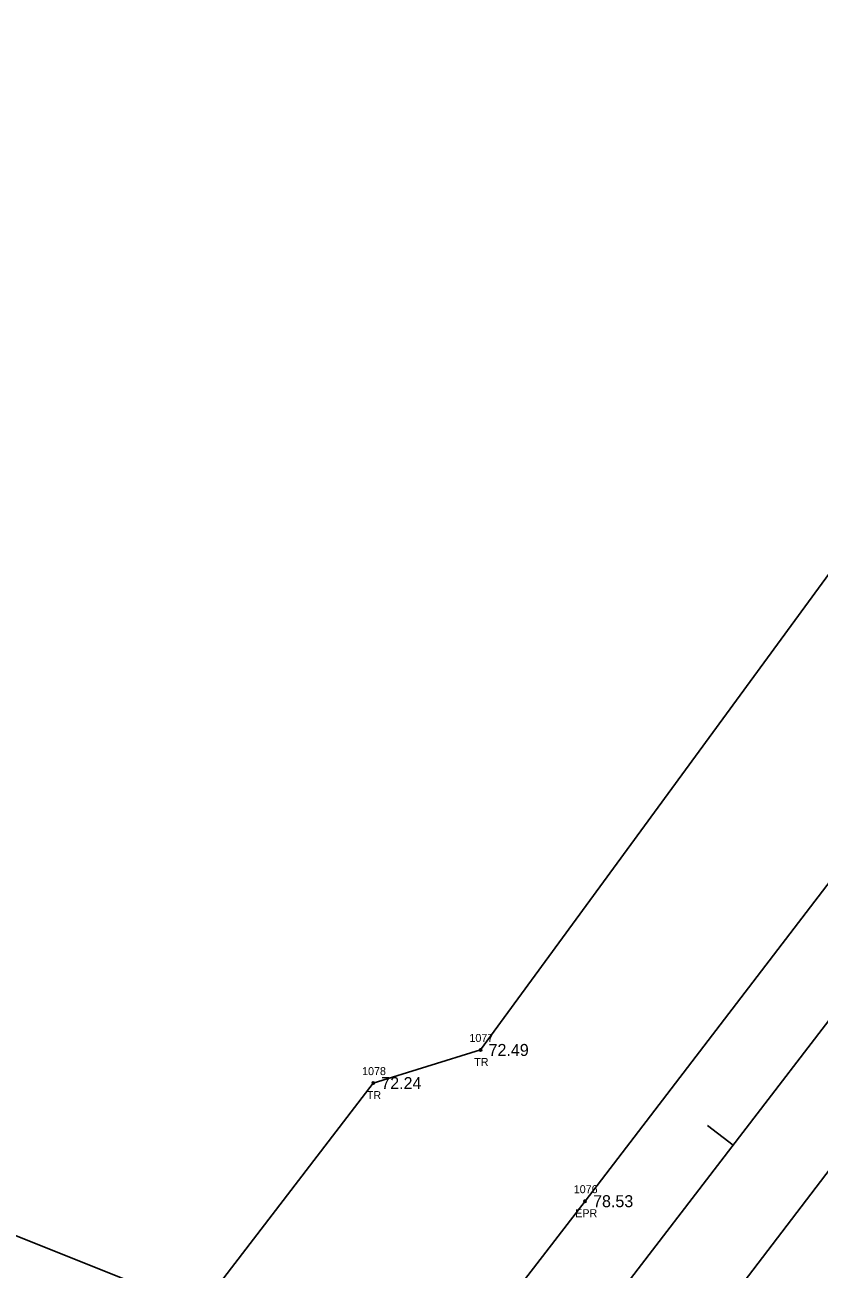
# Model space of a CAD drawing. Extents: x 2505249 to 2506333, y 912937 to 914171.
# Drawn here: x 2505770.9 to 2505870.1, y 913565.9 to 913721.3 of the extents above; entities that cross this region are included whole.
import ezdxf

# ---------------------------------------------------------------- set-up
doc = ezdxf.new("R2010")
doc.units = 0
for name, color, linetype in [('RD_EX_H2O', 7, 'Continuous'), ('RD_EX_Road', 7, 'Continuous'), ('RD_EX_Road_txCode', 7, 'Continuous'), ('RD_EX_TX_Road_ELEV', 7, 'Continuous'), ('RD_EX_TX_VEG_ELEV', 7, 'Continuous'), ('RD_EX_VEG', 7, 'Continuous'), ('RD_EX_VEG_txCode', 7, 'Continuous'), ('RD_HC_Cl', 7, 'Continuous'), ('RD_HC_Data_Tic', 7, 'Continuous'), ('RD_SMD_Locator', 7, 'Continuous')]:
    doc.layers.add(name, color=color, linetype=linetype)

msp = doc.modelspace()

# ---------------------------------------------------------------- linework, layer by layer
at = {"layer": 'RD_EX_H2O'}
msp.add_lwpolyline([(2505762.26, 913658.11), (2505746.15, 913644.25), (2505726.47, 913615.21), (2505674.21, 913628.01), (2505666.25, 913620.58), (2505714.6, 913592.15), (2505793.9, 913560.45), (2505801.32, 913552.8), (2505803.7, 913539.77), (2505832.63, 913516.96), (2505848.42, 913517.19), (2505881.86, 913528.44), (2505910.2, 913538.78), (2505939.3, 913544.45), (2505946.25, 913542.54), (2505974.65, 913535.18), (2506004.11, 913524.7), (2506052.03, 913515.47), (2506115.49, 913494.68), (2506138.05, 913548.89)], dxfattribs=at)
at = {"layer": 'RD_EX_Road'}
for points in [[(2506024.03, 913813.1), (2505962.01, 913732.06), (2505903.3, 913655.93), (2505840.88, 913574.4), (2505819.41, 913546.54), (2505814.19, 913542.64)], [(2506040.71, 913800.23), (2505979.73, 913720.47), (2505920.44, 913642.61), (2505859.42, 913562.61), (2505835.44, 913531.43), (2505833.77, 913527.25)]]:
    msp.add_lwpolyline(points, dxfattribs=at)
at = {"layer": 'RD_EX_VEG'}
msp.add_lwpolyline([(2506002.64, 913815.25), (2505883.7, 913669.64), (2505827.83, 913593.29), (2505814.43, 913589.15), (2505792.49, 913560.55), (2505725.64, 913468.24), (2505664.37, 913399.09), (2505478.33, 913221), (2505411.99, 913152.19), (2505339.13, 913074.53)], dxfattribs=at)
at = {"layer": 'RD_HC_Cl'}
msp.add_line((2505792.76, 913494.51), (2506032.34, 913807.1), dxfattribs=at)
at = {"layer": 'RD_HC_Data_Tic'}
msp.add_line((2505859.37, 913581.41), (2505856.19, 913583.84), dxfattribs=at)
at = {"layer": 'RD_SMD_Locator'}
for centre in [(2505827.83, 913593.29), (2505814.43, 913589.15), (2505840.88, 913574.4)]:
    msp.add_circle(centre, 0.15, dxfattribs=at)

# ---------------------------------------------------------------- texts
at = {"layer": 'RD_EX_Road_txCode'}
for s, p in [('1076', (2505839.47, 913575.4)), ('EPR', (2505839.65, 913572.4))]:
    msp.add_text(s, height=1, dxfattribs=at).set_placement(p)
at = {"layer": 'RD_EX_TX_Road_ELEV'}
msp.add_text('78.53', height=1.5, dxfattribs=at).set_placement((2505841.88, 913573.65))
at = {"layer": 'RD_EX_TX_VEG_ELEV'}
for s, p in [('72.49', (2505828.83, 913592.54)), ('72.24', (2505815.43, 913588.4))]:
    msp.add_text(s, height=1.5, dxfattribs=at).set_placement(p)
at = {"layer": 'RD_EX_VEG_txCode'}
for s, p in [('1077', (2505826.44, 913594.29)), ('TR', (2505827.04, 913591.29)), ('1078', (2505813.04, 913590.15)), ('TR', (2505813.63, 913587.15))]:
    msp.add_text(s, height=1, dxfattribs=at).set_placement(p)

doc.saveas('drawing.dxf')
